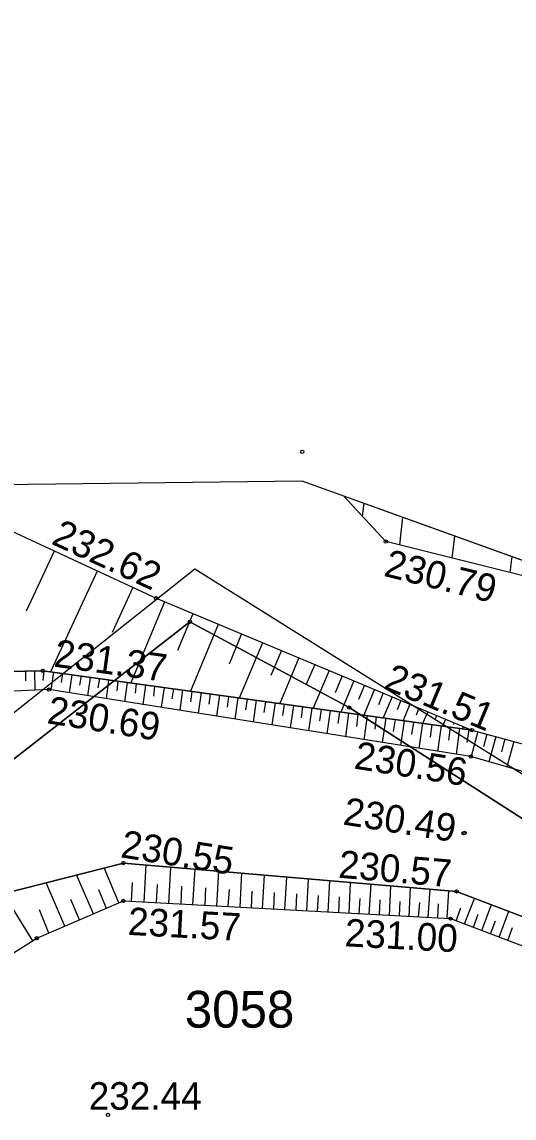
# Model space of a CAD drawing. Extents: x 6596400 to 6597200, y 5539751 to 5540251.
# Drawn here: x 6596748.15 to 6596761.51, y 5540104.16 to 5540133.92 of the extents above; entities that cross this region are included whole.
import ezdxf

# ---------------------------------------------------------------- set-up
doc = ezdxf.new("R2010")
doc.units = 0
for name, color, linetype in [('000 Inne (niezydentyfikowane)', 7, 'Continuous'), ('140-Punkty robocze', 7, 'Continuous'), ('203-punkt graniczny', 7, 'Continuous'), ('211-numer działki ewidencyjnej', 7, 'Continuous'), ('217-kontur klasyfikacyjny', 7, 'Continuous'), ('218-kontur użytku gruntowego', 7, 'Continuous'), ('219-działka ewidencyjna', 7, 'Continuous'), ('Linia obszaru zagospodarowania terenu', 7, 'Continuous'), ('pikieta sztuczna', 7, 'Continuous'), ('pikieta sztuczna-Atr2', 7, 'Continuous'), ('skarpa nieumocniona', 7, 'Continuous'), ('woda płynąca', 7, 'Continuous'), ('Zakres', 7, 'Continuous')]:
    doc.layers.add(name, color=color, linetype=linetype)

# ---------------------------------------------------------------- blocks, each defined once
blk = doc.blocks.new('203')
blk.add_circle((0, 0), 0.045)
blk = doc.blocks.new('PIKIETA')
blk.add_circle((0, 0), 0.045)
blk = doc.blocks.new('PW01')
blk.add_circle((0, 0), 0.045)

msp = doc.modelspace()

# ---------------------------------------------------------------- linework, layer by layer
at = {"layer": '000 Inne (niezydentyfikowane)'}
for p, q in [((6596757.431, 5540120.849), (6596757.39, 5540120.5)), ((6596758.486, 5540120.47), (6596758.4, 5540119.72)), ((6596759.891, 5540119.964), (6596759.82, 5540119.36)), ((6596749.02, 5540119.55), (6596748.26, 5540117.92)), ((6596761.45, 5540119.404), (6596761.4, 5540118.97)), ((6596750.19, 5540119.01), (6596748.92, 5540116.27)), ((6596751.16, 5540118.56), (6596750.6, 5540117.34)), ((6596752.02, 5540118.17), (6596751.1, 5540115.97)), ((6596752.79, 5540117.85), (6596752.37, 5540116.85)), ((6596753.48, 5540117.56), (6596752.72, 5540115.75)), ((6596754.11, 5540117.3), (6596753.77, 5540116.48)), ((6596754.68, 5540117.06), (6596754.05, 5540115.56)), ((6596755.2, 5540116.85), (6596754.91, 5540116.17)), ((6596755.67, 5540116.65), (6596755.15, 5540115.41)), ((6596748.49, 5540116.3), (6596748.5, 5540115.77)), ((6596748.74, 5540116.3), (6596748.71, 5540116.04)), ((6596756.1, 5540116.47), (6596755.86, 5540115.91)), ((6596756.49, 5540116.31), (6596756.06, 5540115.29)), ((6596748.24, 5540116.29), (6596748.24, 5540116.03)), ((6596749, 5540116.26), (6596748.93, 5540115.78)), ((6596749.25, 5540116.23), (6596749.21, 5540115.98)), ((6596749.5, 5540116.19), (6596749.43, 5540115.7)), ((6596749.75, 5540116.16), (6596749.71, 5540115.91)), ((6596750, 5540116.12), (6596749.93, 5540115.62)), ((6596750.25, 5540116.09), (6596750.21, 5540115.84)), ((6596750.5, 5540116.05), (6596750.43, 5540115.54)), ((6596750.75, 5540116.02), (6596750.72, 5540115.76)), ((6596756.84, 5540116.16), (6596756.65, 5540115.7)), ((6596757.16, 5540116.03), (6596756.81, 5540115.18)), ((6596751, 5540115.98), (6596750.93, 5540115.46)), ((6596751.25, 5540115.95), (6596751.22, 5540115.69)), ((6596751.5, 5540115.91), (6596751.43, 5540115.38)), ((6596751.75, 5540115.88), (6596751.72, 5540115.61)), ((6596752.01, 5540115.85), (6596751.93, 5540115.31)), ((6596752.26, 5540115.81), (6596752.22, 5540115.54)), ((6596752.51, 5540115.78), (6596752.43, 5540115.23)), ((6596752.76, 5540115.74), (6596752.72, 5540115.46)), ((6596753.01, 5540115.71), (6596752.93, 5540115.15)), ((6596757.45, 5540115.91), (6596757.29, 5540115.52)), ((6596757.72, 5540115.8), (6596757.43, 5540115.1)), ((6596757.96, 5540115.7), (6596757.83, 5540115.38)), ((6596753.26, 5540115.67), (6596753.22, 5540115.39)), ((6596753.51, 5540115.64), (6596753.43, 5540115.07)), ((6596753.76, 5540115.6), (6596753.72, 5540115.31)), ((6596754.01, 5540115.57), (6596753.93, 5540114.99)), ((6596754.26, 5540115.53), (6596754.22, 5540115.24)), ((6596754.51, 5540115.5), (6596754.43, 5540114.91)), ((6596754.76, 5540115.46), (6596754.72, 5540115.17)), ((6596755.02, 5540115.43), (6596754.93, 5540114.83)), ((6596758.2, 5540115.59), (6596757.96, 5540115.02)), ((6596758.44, 5540115.49), (6596758.34, 5540115.24)), ((6596755.27, 5540115.39), (6596755.22, 5540115.09)), ((6596755.52, 5540115.36), (6596755.43, 5540114.75)), ((6596755.77, 5540115.33), (6596755.73, 5540115.02)), ((6596756.02, 5540115.29), (6596755.93, 5540114.67)), ((6596756.27, 5540115.26), (6596756.23, 5540114.94)), ((6596756.52, 5540115.22), (6596756.43, 5540114.59)), ((6596756.77, 5540115.19), (6596756.73, 5540114.87)), ((6596757.02, 5540115.15), (6596756.93, 5540114.51)), ((6596757.27, 5540115.12), (6596757.23, 5540114.79)), ((6596758.68, 5540115.39), (6596758.5, 5540114.95)), ((6596758.93, 5540115.29), (6596758.85, 5540115.1)), ((6596759.17, 5540115.19), (6596759.03, 5540114.87)), ((6596757.52, 5540115.08), (6596757.43, 5540114.43)), ((6596757.77, 5540115.05), (6596757.73, 5540114.72)), ((6596758.03, 5540115.01), (6596757.93, 5540114.35)), ((6596758.28, 5540114.98), (6596758.23, 5540114.65)), ((6596758.53, 5540114.94), (6596758.43, 5540114.27)), ((6596758.78, 5540114.91), (6596758.73, 5540114.57)), ((6596759.03, 5540114.88), (6596758.93, 5540114.19)), ((6596759.28, 5540114.84), (6596759.23, 5540114.5)), ((6596759.41, 5540115.09), (6596759.36, 5540114.96)), ((6596759.53, 5540114.81), (6596759.43, 5540114.11)), ((6596759.65, 5540114.99), (6596759.57, 5540114.8)), ((6596759.89, 5540114.89), (6596759.86, 5540114.83)), ((6596759.78, 5540114.77), (6596759.73, 5540114.42)), ((6596760.03, 5540114.74), (6596759.94, 5540114.03)), ((6596760.13, 5540114.79), (6596760.11, 5540114.73)), ((6596760.28, 5540114.7), (6596760.23, 5540114.35)), ((6596760.53, 5540114.65), (6596760.35, 5540113.97)), ((6596760.77, 5540114.58), (6596760.68, 5540114.24)), ((6596761.02, 5540114.51), (6596760.83, 5540113.83)), ((6596761.26, 5540114.45), (6596761.17, 5540114.1)), ((6596761.51, 5540114.38), (6596761.32, 5540113.69))]:
    msp.add_line(p, q, dxfattribs=at)
for points in [[(6596750.78, 5540110), (6596750.38, 5540110.95)], [(6596751.47, 5540110.02), (6596751.52, 5540111.03)], [(6596752.14, 5540109.98), (6596752.19, 5540110.97)], [(6596750.09, 5540109.7), (6596749.63, 5540110.76)], [(6596752.79, 5540109.95), (6596752.85, 5540110.91)], [(6596753.44, 5540109.91), (6596753.49, 5540110.86)], [(6596754.07, 5540109.88), (6596754.12, 5540110.81)], [(6596754.68, 5540109.85), (6596754.73, 5540110.75)], [(6596755.29, 5540109.81), (6596755.34, 5540110.7)], [(6596755.88, 5540109.78), (6596755.93, 5540110.65)], [(6596749.31, 5540109.37), (6596748.8, 5540110.54)], [(6596750.44, 5540109.85), (6596750.23, 5540110.35)], [(6596751.12, 5540110.04), (6596751.15, 5540110.55)], [(6596751.8, 5540110), (6596751.83, 5540110.5)], [(6596752.47, 5540109.97), (6596752.49, 5540110.45)], [(6596753.12, 5540109.93), (6596753.14, 5540110.41)], [(6596753.75, 5540109.9), (6596753.78, 5540110.36)], [(6596756.46, 5540109.75), (6596756.51, 5540110.6)], [(6596757.03, 5540109.72), (6596757.07, 5540110.55)], [(6596757.58, 5540109.69), (6596757.63, 5540110.51)], [(6596758.13, 5540109.66), (6596758.17, 5540110.46)], [(6596758.66, 5540109.63), (6596758.7, 5540110.42)], [(6596759.18, 5540109.6), (6596759.23, 5540110.37)], [(6596748.44, 5540108.97), (6596747.65, 5540110.24)], [(6596749.71, 5540109.54), (6596749.47, 5540110.09)], [(6596754.38, 5540109.86), (6596754.4, 5540110.32)], [(6596754.99, 5540109.83), (6596755.01, 5540110.28)], [(6596755.59, 5540109.8), (6596755.61, 5540110.24)], [(6596756.17, 5540109.77), (6596756.2, 5540110.2)], [(6596756.75, 5540109.73), (6596756.77, 5540110.16)], [(6596757.31, 5540109.7), (6596757.33, 5540110.12)], [(6596757.86, 5540109.67), (6596757.88, 5540110.08)], [(6596759.7, 5540109.58), (6596759.74, 5540110.33)], [(6596760.17, 5540109.43), (6596760.44, 5540110.12)], [(6596748.88, 5540109.18), (6596748.62, 5540109.81)], [(6596758.4, 5540109.65), (6596758.42, 5540110.04)], [(6596758.92, 5540109.62), (6596758.95, 5540110.01)], [(6596759.44, 5540109.59), (6596759.46, 5540109.97)], [(6596759.94, 5540109.51), (6596760.07, 5540109.86)], [(6596760.64, 5540109.25), (6596760.9, 5540109.95)], [(6596761.11, 5540109.07), (6596761.37, 5540109.77)], [(6596760.41, 5540109.34), (6596760.54, 5540109.69)], [(6596760.87, 5540109.16), (6596761.01, 5540109.51)], [(6596761.34, 5540108.98), (6596761.47, 5540109.33)]]:
    msp.add_lwpolyline(points, dxfattribs=at)
at = {"layer": '217-kontur klasyfikacyjny'}
for points in [[(6596742.6, 5540109.76), (6596752.71, 5540117.63)], [(6596752.71, 5540117.63), (6596757.03, 5540115.3)], [(6596757.03, 5540115.3), (6596766.66, 5540109.13)]]:
    msp.add_lwpolyline(points, dxfattribs=at)
at = {"layer": '218-kontur użytku gruntowego'}
for points in [[(6596742.6, 5540109.76), (6596752.71, 5540117.63)], [(6596752.71, 5540117.63), (6596742.6, 5540109.76)], [(6596752.71, 5540117.63), (6596757.03, 5540115.3)], [(6596757.03, 5540115.3), (6596752.71, 5540117.63)], [(6596757.03, 5540115.3), (6596766.66, 5540109.13)], [(6596766.66, 5540109.13), (6596757.03, 5540115.3)]]:
    msp.add_lwpolyline(points, dxfattribs=at)
at = {"layer": '219-działka ewidencyjna'}
for points in [[(6596742.6, 5540109.76), (6596752.71, 5540117.63)], [(6596757.03, 5540115.3), (6596752.71, 5540117.63)], [(6596766.66, 5540109.13), (6596757.03, 5540115.3)]]:
    msp.add_lwpolyline(points, dxfattribs=at)
at = {"layer": 'Linia obszaru zagospodarowania terenu'}
msp.add_lwpolyline([(6596781.725, 5540112.112), (6596780.93, 5540109.34), (6596777.59, 5540106.98), (6596766.77, 5540110.34), (6596752.84, 5540119.06), (6596742.54, 5540110.89), (6596731.18, 5540096.66), (6596730.7, 5540082.79)], dxfattribs=at)
at = {"layer": 'skarpa nieumocniona'}
for points in [[(6596751.79, 5540118.27), (6596760.37, 5540114.69), (6596748.71, 5540116.3), (6596743.9, 5540116.21), (6596740.41, 5540117.83), (6596735.6, 5540111.55), (6596736.12, 5540109.87), (6596735.55, 5540098.25), (6596728.64, 5540097.09), (6596724.81, 5540103.41), (6596724.02, 5540108.52), (6596725.61, 5540113.6), (6596728.6, 5540116.52), (6596734.94, 5540121.2), (6596745.21, 5540121.32)], [(6596751.79, 5540118.27), (6596760.37, 5540114.69), (6596748.71, 5540116.3), (6596743.9, 5540116.21), (6596740.41, 5540117.83), (6596735.6, 5540111.55), (6596736.12, 5540109.87), (6596735.55, 5540098.25), (6596728.64, 5540097.09), (6596724.81, 5540103.41), (6596724.02, 5540108.52), (6596725.61, 5540113.6), (6596728.6, 5540116.52), (6596734.94, 5540121.2), (6596745.21, 5540121.32)], [(6596765.53, 5540117.94), (6596758.03, 5540119.81), (6596756.88, 5540121.05)], [(6596765.53, 5540117.94), (6596758.03, 5540119.81), (6596756.88, 5540121.05)], [(6596742.42, 5540096.36), (6596740.92, 5540088.42), (6596741.25, 5540084.94), (6596741.25, 5540084.94), (6596742.75, 5540092.05), (6596743.5, 5540096.22), (6596744.79, 5540102.47), (6596745.19, 5540106.93), (6596748.55, 5540109.04), (6596750.9, 5540110.05), (6596759.79, 5540109.57), (6596764.72, 5540107.7), (6596768.41, 5540103.97), (6596769.44, 5540104.84), (6596765.11, 5540108.34), (6596759.95, 5540110.31), (6596750.9, 5540111.08), (6596747.66, 5540110.25), (6596744.49, 5540107.55), (6596743.6, 5540103.66)], [(6596742.42, 5540096.36), (6596740.92, 5540088.42), (6596741.25, 5540084.94), (6596741.25, 5540084.94), (6596742.75, 5540092.05), (6596743.5, 5540096.22), (6596744.79, 5540102.47), (6596745.19, 5540106.93), (6596748.55, 5540109.04), (6596750.9, 5540110.05), (6596759.79, 5540109.57), (6596764.72, 5540107.7), (6596768.41, 5540103.97), (6596769.44, 5540104.84), (6596765.11, 5540108.34), (6596759.95, 5540110.31), (6596750.9, 5540111.08), (6596747.66, 5540110.25), (6596744.49, 5540107.55), (6596743.6, 5540103.66)]]:
    msp.add_lwpolyline(points, close=True, dxfattribs=at)
for points in [[(6596736.14, 5540074.83), (6596735.19, 5540080.23), (6596735.33, 5540085.41), (6596734.65, 5540089.1), (6596735.44, 5540093.45), (6596735.8, 5540095.62), (6596737, 5540098.15), (6596738.35, 5540109.49), (6596736.12, 5540109.87), (6596735.6, 5540111.55), (6596739.06, 5540111.12), (6596739.7, 5540112.38), (6596741.35, 5540114.97), (6596743.9, 5540116.21), (6596748.71, 5540116.3), (6596760.37, 5540114.69), (6596767.09, 5540112.87), (6596773.08, 5540108.54), (6596778.11, 5540104.44), (6596785.94, 5540101.26), (6596790.69, 5540099.45)], [(6596736.14, 5540074.83), (6596735.19, 5540080.23), (6596735.33, 5540085.41), (6596734.65, 5540089.1), (6596735.44, 5540093.45), (6596735.8, 5540095.62), (6596737, 5540098.15), (6596738.35, 5540109.49), (6596736.12, 5540109.87), (6596735.6, 5540111.55), (6596739.06, 5540111.12), (6596739.7, 5540112.38), (6596741.35, 5540114.97), (6596743.9, 5540116.21), (6596748.71, 5540116.3), (6596760.37, 5540114.69), (6596767.09, 5540112.87), (6596773.08, 5540108.54), (6596778.11, 5540104.44), (6596785.94, 5540101.26), (6596790.69, 5540099.45)], [(6596790.15, 5540098.33), (6596785.05, 5540099.81), (6596777.76, 5540103.71), (6596772.25, 5540107.73), (6596766.79, 5540112.11), (6596760.34, 5540113.97), (6596748.88, 5540115.79), (6596744.15, 5540115.57), (6596742.04, 5540114.13), (6596740.39, 5540112.04), (6596739.35, 5540110.21), (6596737.64, 5540097.87), (6596736.29, 5540093.37), (6596736.04, 5540089.3), (6596736.53, 5540085.88), (6596736.56, 5540080.1), (6596736.48, 5540078.77)], [(6596790.15, 5540098.33), (6596785.05, 5540099.81), (6596777.76, 5540103.71), (6596772.25, 5540107.73), (6596766.79, 5540112.11), (6596760.34, 5540113.97), (6596748.88, 5540115.79), (6596744.15, 5540115.57), (6596742.04, 5540114.13), (6596740.39, 5540112.04), (6596739.35, 5540110.21), (6596737.64, 5540097.87), (6596736.29, 5540093.37), (6596736.04, 5540089.3), (6596736.53, 5540085.88), (6596736.56, 5540080.1), (6596736.48, 5540078.77)]]:
    msp.add_lwpolyline(points, dxfattribs=at)
at = {"layer": 'woda płynąca'}
for points in [[(6596801.146, 5540105.126), (6596800.55, 5540103.15), (6596798.59, 5540101.49), (6596797.54, 5540099.56), (6596796.12, 5540099.28), (6596790.15, 5540098.33), (6596785.05, 5540099.81), (6596777.76, 5540103.71), (6596772.25, 5540107.73), (6596766.79, 5540112.11), (6596760.34, 5540113.97), (6596748.88, 5540115.79), (6596744.15, 5540115.57), (6596742.04, 5540114.13), (6596740.39, 5540112.04), (6596739.35, 5540110.21), (6596737.64, 5540097.87), (6596736.29, 5540093.37), (6596736.04, 5540089.3), (6596736.53, 5540085.88)], [(6596746.88, 5540042.02), (6596743.2, 5540046.89), (6596742.01, 5540050.53), (6596741.65, 5540054.82), (6596742.47, 5540061.97), (6596743.25, 5540066.3), (6596741.68, 5540074.92), (6596740.68, 5540078.45), (6596740.72, 5540079.85), (6596740.91, 5540084.82), (6596741.25, 5540084.94), (6596740.92, 5540088.42), (6596742.42, 5540096.36), (6596743.6, 5540103.66), (6596744.49, 5540107.55), (6596747.66, 5540110.25), (6596750.9, 5540111.08), (6596759.95, 5540110.31), (6596765.11, 5540108.34), (6596769.44, 5540104.84), (6596775.99, 5540100.07), (6596783.39, 5540096.06), (6596790.43, 5540094.51)]]:
    msp.add_lwpolyline(points, dxfattribs=at)
at = {"layer": 'Zakres'}
msp.add_lwpolyline([(6596822.22, 5540097.5), (6596800.39, 5540105.4), (6596755.76, 5540121.45), (6596697.73, 5540120.74), (6596659.35, 5540133.92), (6596647.64, 5540109.28), (6596697.73, 5540077), (6596721.01, 5540057.77), (6596727.72, 5540045.95), (6596731.95, 5540033.61), (6596741.17, 5540031.18), (6596755.59, 5540029.2), (6596757.85, 5540044.22), (6596787.25, 5540055.04), (6596806.3, 5540048.33), (6596813.97, 5540042.6), (6596833.15, 5540068.58), (6596822.3, 5540077.75)], close=True, dxfattribs=at)

# ---------------------------------------------------------------- block references
at = {"layer": '140-Punkty robocze'}
for p in [(6596755.76, 5540122.25), (6596758.03, 5540119.81), (6596751.79, 5540118.27), (6596748.71, 5540116.3), (6596748.88, 5540115.79), (6596760.37, 5540114.69), (6596760.34, 5540113.97), (6596760.14, 5540111.89), (6596760.17, 5540111.9), (6596750.9, 5540111.08), (6596759.95, 5540110.31), (6596750.9, 5540110.05), (6596759.79, 5540109.57), (6596748.55, 5540109.04), (6596750.48, 5540104.24)]:
    msp.add_blockref('PIKIETA', p, dxfattribs=at)
at = {"layer": '203-punkt graniczny'}
for p in [(6596752.71, 5540117.63), (6596757.03, 5540115.3)]:
    msp.add_blockref('203', p, dxfattribs=at)
at = {"layer": 'pikieta sztuczna'}
for p in [(6596758.03, 5540119.81), (6596751.79, 5540118.27), (6596748.71, 5540116.3), (6596748.88, 5540115.79), (6596760.37, 5540114.69), (6596760.34, 5540113.97), (6596760.14, 5540111.89), (6596750.9, 5540111.08), (6596759.95, 5540110.31), (6596750.9, 5540110.05), (6596759.79, 5540109.57), (6596750.48, 5540104.24)]:
    msp.add_blockref('PW01', p, dxfattribs=at)

# ---------------------------------------------------------------- texts
at = {"layer": '211-numer działki ewidencyjnej'}
msp.add_text('3058', height=1, dxfattribs=at).set_placement((6596752.57, 5540106.61))
at = {"layer": 'pikieta sztuczna-Atr2'}
for s, rotation, p in [('232.62', 335.11, (6596748.914, 5540119.76)), ('230.79', 345.976, (6596757.948, 5540118.882)), ('231.37', 352.138, (6596748.987, 5540116.417)), ('231.51', 337.352, (6596757.941, 5540115.828)), ('230.69', 350.976, (6596748.802, 5540114.879)), ('230.56', 350.976, (6596757.142, 5540113.649)), ('230.49', 350.976, (6596756.842, 5540112.129)), ('230.55', 350.976, (6596750.802, 5540111.239)), ('230.57', 355.137, (6596756.726, 5540110.683)), ('231.57', 356.909, (6596751.01, 5540109.131)), ('231.00', 356.909, (6596756.9, 5540108.821))]:
    msp.add_text(s, height=0.75, rotation=rotation, dxfattribs=at).set_placement(p)
msp.add_text('232.44', height=0.75, dxfattribs=at).set_placement((6596749.96, 5540104.38))

doc.saveas('drawing.dxf')
